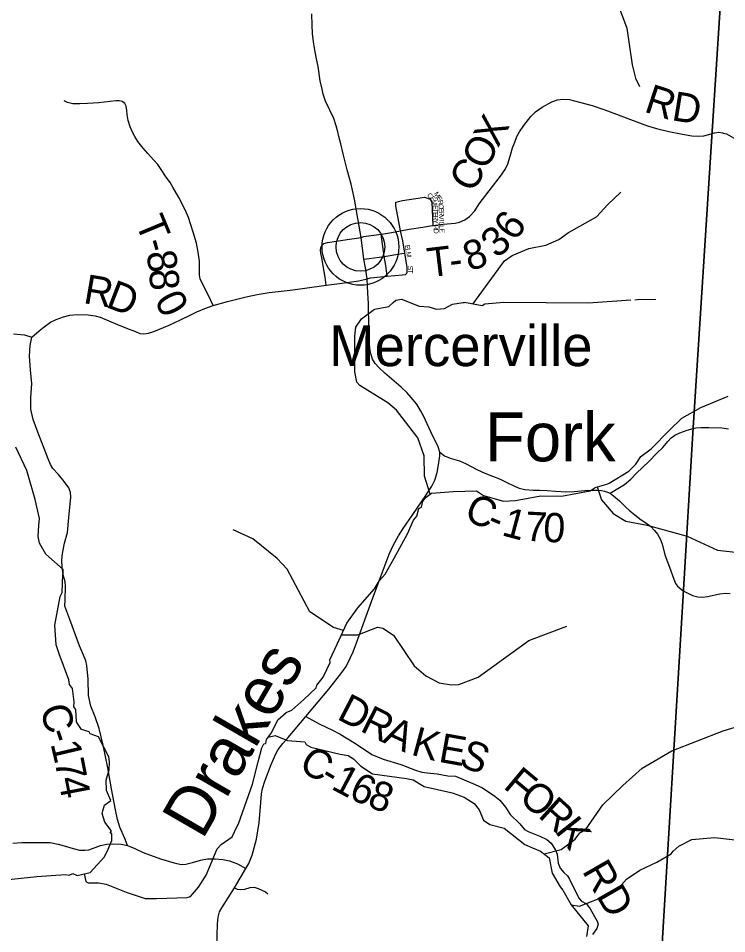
# Model space of a CAD drawing. Extents: x -1.8 to 75.7, y -2 to 25.
# Drawn here: x 46.582 to 47.955, y 16.82 to 18.595 of the extents above; entities that cross this region are included whole.
import ezdxf

# ---------------------------------------------------------------- set-up
doc = ezdxf.new("R2010")
doc.units = 0
for name, color, linetype in [('GM_X_County_Road', 7, 'Continuous'), ('GM_X_County_Road_Text', 7, 'Continuous'), ('GM_X_Minor_River', 7, 'Continuous'), ('GM_X_Minor_River_Text', 7, 'Continuous'), ('GM_X_State_Route', 7, 'Continuous'), ('GM_X_Township', 7, 'Continuous'), ('GM_X_Township_Road', 7, 'Continuous'), ('GM_X_Township_Road_Text', 7, 'Continuous'), ('GM_X_Township_Subdivision', 7, 'Continuous'), ('GM_X_Township_Subdivision_Text', 7, 'Continuous'), ('GM_X_Unincorporated', 7, 'Continuous'), ('GM_X_Unincorporated_Location', 7, 'Continuous'), ('GM_X_Unincorporated_Text', 7, 'Continuous')]:
    doc.layers.add(name, color=color, linetype=linetype)

msp = doc.modelspace()

# ---------------------------------------------------------------- linework, layer by layer
at = {"layer": 'GM_X_County_Road'}
for points in [[(46.9314, 18.0271), (46.9439, 18.032), (46.9596, 18.038), (46.9876, 18.0457), (47.0236, 18.0547), (47.0452, 18.0594), (47.0686, 18.0629), (47.1088, 18.0679), (47.1373, 18.0714), (47.1791, 18.0773), (47.2048, 18.0808), (47.2424, 18.0858), (47.2582, 18.0897)], [(46.5726, 17.9832), (46.5938, 17.9811), (46.6081, 17.9768), (46.6226, 17.9887), (46.6323, 17.9969), (46.6447, 18.0055), (46.6552, 18.0108), (46.6694, 18.016), (46.682, 18.019), (46.6968, 18.0207), (46.7173, 18.0198), (46.7308, 18.0181), (46.7409, 18.0153), (46.7576, 18.0083), (46.7743, 18.001), (46.7917, 17.9941), (46.809, 17.9877), (46.8176, 17.9834), (46.8251, 17.983), (46.8343, 17.9845), (46.8448, 17.9879), (46.8743, 18.0001), (46.8966, 18.01), (46.9167, 18.02), (46.9294, 18.0262), (46.9314, 18.0271)], [(46.7936, 16.9909), (46.7883, 17.0042), (46.7788, 17.0262), (46.7744, 17.0411), (46.7707, 17.0601), (46.7628, 17.101), (46.7557, 17.1412), (46.7469, 17.1857), (46.7388, 17.2178), (46.7311, 17.2402), (46.7229, 17.2611), (46.7179, 17.2818), (46.7177, 17.3135), (46.7152, 17.3397), (46.7133, 17.3489), (46.7084, 17.3599), (46.7007, 17.3782), (46.682, 17.4292), (46.6726, 17.4547), (46.673, 17.467), (46.6734, 17.4928), (46.6732, 17.5024), (46.6699, 17.5134), (46.6673, 17.5299), (46.6664, 17.5451), (46.6675, 17.5572), (46.6719, 17.5772), (46.6772, 17.5975), (46.68, 17.6272), (46.684, 17.6663), (46.6833, 17.6754), (46.68, 17.6844), (46.671, 17.6969), (46.6602, 17.7103), (46.6492, 17.722), (46.6448, 17.7299), (46.6402, 17.7407), (46.62, 17.7924), (46.611, 17.817), (46.6066, 17.837), (46.6066, 17.8599), (46.6081, 17.8859), (46.6059, 17.9134), (46.6039, 17.9396), (46.605, 17.9602), (46.6081, 17.9768)], [(47.399, 17.7533), (47.4085, 17.7467), (47.4191, 17.7422), (47.4374, 17.7368), (47.4491, 17.7314), (47.4707, 17.7199), (47.4866, 17.7127), (47.501, 17.7072), (47.5147, 17.7016), (47.528, 17.6957), (47.5436, 17.6876), (47.5528, 17.6838), (47.5639, 17.6811), (47.5804, 17.6801), (47.5922, 17.6801), (47.6075, 17.6793), (47.6231, 17.6779), (47.6432, 17.6767), (47.6595, 17.6772), (47.6802, 17.679), (47.6945, 17.6799), (47.7044, 17.6799), (47.7125, 17.679), (47.7186, 17.6779), (47.7241, 17.6761), (47.7291, 17.6743), (47.736, 17.6689), (47.7473, 17.6589), (47.7595, 17.6469), (47.7672, 17.6397), (47.7769, 17.6322), (47.7894, 17.6226), (47.7988, 17.6167), (47.8081, 17.6094), (47.8156, 17.6015), (47.8212, 17.5943), (47.8269, 17.5841), (47.8309, 17.5735), (47.8354, 17.5545), (47.8445, 17.5304), (47.8528, 17.5076), (47.856, 17.4992), (47.8599, 17.4935), (47.868, 17.4868), (47.8714, 17.4849), (47.8758, 17.4823)], [(47.8758, 17.4823), (47.8773, 17.4814), (47.8892, 17.4759), (47.8996, 17.473), (47.9086, 17.4726), (47.9181, 17.4739), (47.9418, 17.4789), (47.9527, 17.4804), (47.9617, 17.4796)], [(47.1395, 17.2413), (47.165, 17.227), (47.191, 17.2146), (47.206, 17.2065), (47.2324, 17.1905), (47.251, 17.178), (47.2672, 17.1674), (47.2895, 17.1584), (47.3237, 17.1482), (47.3518, 17.137), (47.3645, 17.133), (47.3744, 17.1319), (47.3941, 17.13), (47.4146, 17.126), (47.4294, 17.1252), (47.4461, 17.1184), (47.4674, 17.1093), (47.4816, 17.1026), (47.5061, 17.0863), (47.5156, 17.0789), (47.5262, 17.065), (47.5353, 17.0508), (47.5545, 17.033), (47.5635, 17.0217), (47.5703, 17.018), (47.5927, 17.0092), (47.6065, 17.0028), (47.6153, 16.9952), (47.6234, 16.9819), (47.6268, 16.9739), (47.6287, 16.9563), (47.6322, 16.9468), (47.6394, 16.9382), (47.6468, 16.9318), (47.6508, 16.9253), (47.6631, 16.9003), (47.6694, 16.8881), (47.6739, 16.8828), (47.6832, 16.8775), (47.6904, 16.8678), (47.7039, 16.8441), (47.7064, 16.8384), (47.7035, 16.83), (47.6954, 16.8181)], [(46.5718, 16.9953), (46.589, 16.9966), (46.6277, 16.9966), (46.6439, 16.9966), (46.6596, 16.9933), (46.6752, 16.9889), (46.6837, 16.9863), (46.7009, 16.9815), (46.711, 16.9815), (46.7191, 16.9826), (46.7313, 16.9872), (46.7412, 16.9907), (46.7536, 16.9935), (46.7652, 16.9942), (46.7816, 16.9933), (46.7936, 16.9909), (46.808, 16.9848), (46.824, 16.9773), (46.8579, 16.9651), (46.8839, 16.9575), (46.8981, 16.9542), (46.9066, 16.9546), (46.9195, 16.9577), (46.935, 16.9623), (46.9488, 16.9647), (46.9634, 16.9649), (46.9785, 16.9636), (46.9916, 16.9609), (47.0069, 16.955), (47.0231, 16.9461)]]:
    msp.add_lwpolyline(points, dxfattribs=at)
at = {"layer": 'GM_X_Minor_River'}
for points in [[(47.6284, 18.7505), (47.6904, 18.7156), (47.7165, 18.6675), (47.7418, 18.6293), (47.7619, 18.5758), (47.7722, 18.5049), (47.7784, 18.4791), (47.7861, 18.4628)], [(47.4633, 18.0407), (47.5246, 18.1243), (47.5393, 18.1352), (47.5715, 18.1486), (47.6046, 18.1552), (47.6298, 18.1658), (47.6484, 18.1796), (47.7026, 18.2101), (47.7249, 18.2337), (47.7498, 18.2576)], [(47.3806, 17.6723), (47.3695, 17.707), (47.3688, 17.7462), (47.3566, 17.7811), (47.3151, 17.8348), (47.2982, 17.849), (47.2544, 17.8763), (47.244, 17.8831), (47.2386, 17.8893), (47.2342, 17.9092), (47.2344, 17.9783), (47.2361, 17.9961), (47.2472, 18.0124), (47.2723, 18.031), (47.3001, 18.0358), (47.309, 18.0435), (47.3137, 18.0483), (47.3251, 18.0502), (47.3594, 18.0366), (47.3776, 18.0356), (47.3929, 18.0309), (47.4081, 18.032), (47.4238, 18.0406), (47.4443, 18.0437), (47.4473, 18.0436)], [(47.7697, 18.0481), (47.6874, 18.0428), (47.5233, 18.0435), (47.4866, 18.0408), (47.4812, 18.0376), (47.447, 18.0436)], [(47.8178, 18.0497), (47.782, 18.0489), (47.777, 18.0486)], [(46.7096, 16.9357), (46.7132, 16.9213), (46.7178, 16.9186), (46.7374, 16.9183), (46.7522, 16.916), (46.7911, 16.9002), (46.8282, 16.8881), (46.8501, 16.8881), (46.9095, 16.8898), (46.9159, 16.8921), (46.9317, 16.91), (46.9465, 16.9336), (46.9676, 16.9842), (46.9751, 16.993), (46.9967, 17.0074), (47.0065, 17.0284), (47.0091, 17.0326), (47.0359, 17.1101), (47.0472, 17.1531), (47.054, 17.1801), (47.0581, 17.1877), (47.0619, 17.1889), (47.0634, 17.1961), (47.0732, 17.2094), (47.0849, 17.2345), (47.1015, 17.249), (47.1121, 17.2532), (47.1355, 17.2738), (47.1597, 17.2963), (47.1608, 17.302), (47.1714, 17.3149), (47.1737, 17.3187), (47.1869, 17.3457), (47.1861, 17.3511), (47.2001, 17.3815), (47.2189, 17.4222), (47.2405, 17.4515), (47.2726, 17.4888), (47.282, 17.5045), (47.293, 17.517), (47.3107, 17.5482), (47.3364, 17.595), (47.348, 17.6217), (47.3545, 17.6297), (47.3586, 17.6445), (47.3635, 17.6468), (47.3665, 17.6586), (47.373, 17.6662), (47.3752, 17.6685), (47.3832, 17.6742), (47.4247, 17.6773), (47.4701, 17.6789), (47.4837, 17.6695), (47.5223, 17.6585), (47.5457, 17.6601), (47.5952, 17.669), (47.6353, 17.6683), (47.6909, 17.6787), (47.7003, 17.6852), (47.7226, 17.6913), (47.7271, 17.6932), (47.7657, 17.7165), (47.7789, 17.7302), (47.7887, 17.7451), (47.8091, 17.7603), (47.8442, 17.7961), (47.868, 17.8197), (47.9051, 17.8403), (47.958, 17.8621)], [(46.6614, 17.3624), (46.6553, 17.3802), (46.6527, 17.4179), (46.6632, 17.4738), (46.667, 17.4814), (46.6681, 17.5171), (46.6692, 17.5194), (46.6688, 17.5258), (46.6352, 17.5558), (46.623, 17.577), (46.6204, 17.59), (46.6222, 17.6112), (46.623, 17.6249), (46.615, 17.6621), (46.5987, 17.718), (46.5775, 17.7635)], [(47.704, 17.6862), (47.7124, 17.6613), (47.7354, 17.6348), (47.7598, 17.6197), (47.8008, 17.612), (47.8787, 17.5904), (47.9373, 17.5637), (48.008, 17.5557), (48.0418, 17.5475), (48.0547, 17.5407), (48.0677, 17.5252), (48.0895, 17.498), (48.1198, 17.4481), (48.1434, 17.4315), (48.1571, 17.4262), (48.2033, 17.3938), (48.2139, 17.3885), (48.2371, 17.3841), (48.2523, 17.3827), (48.3137, 17.3974)], [(47.2123, 17.4078), (47.1929, 17.4133), (47.1472, 17.4439), (47.103, 17.5264), (47.0839, 17.5476), (47.0366, 17.5853), (46.9986, 17.603)], [(47.2083, 17.3993), (47.24, 17.3992), (47.2786, 17.4145), (47.2885, 17.4123), (47.3095, 17.3987), (47.3497, 17.3393), (47.3722, 17.3201), (47.3981, 17.3066), (47.422, 17.3021), (47.4357, 17.303), (47.4732, 17.3176), (47.5718, 17.3887), (47.6452, 17.4164)], [(46.5575, 16.9243), (46.618, 16.9306), (46.6735, 16.9349), (46.6807, 16.9334), (46.6879, 16.9364), (46.6962, 16.9326), (46.7212, 16.9384), (46.7491, 16.9692), (46.7563, 16.9837), (46.7631, 17.0004), (46.7634, 17.0141), (46.7604, 17.0149), (46.7623, 17.0183), (46.7619, 17.0202), (46.7498, 17.0361), (46.7449, 17.0532), (46.746, 17.0578), (46.7494, 17.0692), (46.7615, 17.078), (46.7528, 17.0973), (46.7524, 17.1175), (46.7584, 17.1376), (46.7591, 17.1528), (46.7576, 17.1627), (46.7375, 17.2018), (46.7213, 17.2075), (46.7194, 17.2116), (46.7046, 17.2158), (46.6967, 17.2276), (46.6948, 17.2306), (46.6936, 17.2545), (46.6895, 17.2595), (46.6902, 17.2697), (46.6872, 17.2952), (46.6811, 17.3032), (46.68, 17.3123), (46.6614, 17.3624)], [(47.6013, 16.9744), (47.6346, 16.9831), (47.6614, 17.0034), (47.6705, 17.0152), (47.6814, 17.0213), (47.7149, 17.0697), (47.7542, 17.1075), (47.7915, 17.1411), (47.849, 17.1744), (47.9482, 17.2129), (47.9865, 17.2249), (48.0221, 17.2304)], [(47.0667, 17.2012), (47.0798, 17.2041), (47.1041, 17.1942), (47.1373, 17.1916), (47.1398, 17.187), (47.1494, 17.1814), (47.2063, 17.1678)], [(47.2063, 17.1678), (47.2215, 17.1654), (47.2319, 17.159), (47.2458, 17.1445), (47.2688, 17.1297), (47.3343, 17.1208), (47.3475, 17.1181), (47.369, 17.1052), (47.4204, 17.0937), (47.4249, 17.0924), (47.4466, 17.0845), (47.4655, 17.0722), (47.4757, 17.0601), (47.4838, 17.0397), (47.496, 17.0313), (47.5238, 17.0243), (47.564, 16.9927), (47.5786, 16.9861), (47.5943, 16.98), (47.6109, 16.9669), (47.6171, 16.9371), (47.6326, 16.9104), (47.6377, 16.9045), (47.6535, 16.8759), (47.687, 16.835), (47.6834, 16.8146)], [(47.6537, 16.8756), (47.67, 16.8731), (47.7259, 16.8949), (47.7514, 16.9149), (47.7612, 16.9253), (47.787, 16.943), (47.8196, 16.9583), (47.8474, 16.9749), (47.8513, 16.9801), (47.8625, 16.9896), (47.8875, 17.0025), (47.9318, 17.0064), (47.9718, 17.0017)]]:
    msp.add_lwpolyline(points, dxfattribs=at)
at = {"layer": 'GM_X_State_Route'}
for points in [[(47.3918, 17.7721), (47.3849, 17.7862), (47.3679, 17.8226), (47.3619, 17.8344), (47.3543, 17.8464), (47.3437, 17.8598), (47.3353, 17.869), (47.3244, 17.8794), (47.2924, 17.9067), (47.2813, 17.9174), (47.2741, 17.9255), (47.2689, 17.9338), (47.2666, 17.9404), (47.2646, 17.9467), (47.2635, 17.9555), (47.2623, 17.97), (47.2614, 17.996), (47.2606, 18.0415), (47.2598, 18.0626), (47.2591, 18.0758), (47.2582, 18.0897), (47.255, 18.1113), (47.2518, 18.1278), (47.2465, 18.1698), (47.2356, 18.2326), (47.2341, 18.2411), (47.2312, 18.2557), (47.2273, 18.2732), (47.2198, 18.3014), (47.2119, 18.3321), (47.2072, 18.3517), (47.2034, 18.366), (47.2015, 18.3748), (47.198, 18.3863), (47.1934, 18.4005), (47.186, 18.4171), (47.1778, 18.4344), (47.1729, 18.4478), (47.1708, 18.4575), (47.1675, 18.4735), (47.1631, 18.5013), (47.1602, 18.5162), (47.1577, 18.5296), (47.1544, 18.5496), (47.1526, 18.5652), (47.1517, 18.5815), (47.151, 18.6034)], [(47.3825, 17.6859), (47.3837, 17.6876), (47.3892, 17.699), (47.3939, 17.7142), (47.3968, 17.7289), (47.399, 17.7463), (47.399, 17.7533), (47.3958, 17.7639), (47.3918, 17.7721)], [(46.9667, 16.7953), (46.968, 16.839), (46.9693, 16.8519), (46.9722, 16.8624), (46.9766, 16.8702), (47.001, 16.9089), (47.0231, 16.9461), (47.0287, 16.9559), (47.0357, 16.972), (47.0439, 17.003), (47.0492, 17.0356), (47.0518, 17.066), (47.0537, 17.0909), (47.0556, 17.1017), (47.0597, 17.1154), (47.0722, 17.148), (47.0811, 17.1687), (47.086, 17.1769), (47.0949, 17.1884), (47.1049, 17.2002), (47.1395, 17.2413), (47.1633, 17.2694), (47.1839, 17.2942), (47.2095, 17.3261), (47.2175, 17.3382), (47.2263, 17.3554), (47.231, 17.3664), (47.2375, 17.3838), (47.2668, 17.4643), (47.2875, 17.5195), (47.301, 17.556), (47.3088, 17.5729), (47.319, 17.5912), (47.3284, 17.6057), (47.3468, 17.6325), (47.3718, 17.6695), (47.3825, 17.6859)]]:
    msp.add_lwpolyline(points, dxfattribs=at)
at = {"layer": 'GM_X_Township'}
for points in [[(47.7632, 15.7121), (47.7893, 16.1371), (47.8138, 16.5363), (47.826, 16.7363), (47.8708, 17.4759), (47.8899, 17.791), (47.9266, 18.366), (47.9522, 18.7663), (47.1815, 18.806), (46.9192, 18.8195), (46.3714, 18.8466), (46.1197, 18.859), (45.3865, 18.8952), (44.8356, 18.9224), (43.8002, 18.978)], [(50.6002, 18.6397), (50.591, 18.6401), (50.1896, 18.6602), (49.0051, 18.7193), (48.8964, 18.7242), (47.9522, 18.7663), (47.9266, 18.366), (47.8899, 17.791), (47.8708, 17.4759), (47.826, 16.7363), (47.8138, 16.5363), (47.7893, 16.1371), (47.7632, 15.7121)]]:
    msp.add_lwpolyline(points, dxfattribs=at)
at = {"layer": 'GM_X_Township_Road'}
for points in [[(46.9335, 18.1048), (46.9334, 18.1091), (46.9334, 18.1241), (46.9309, 18.1413), (46.9274, 18.159), (46.9212, 18.1804), (46.9122, 18.2085), (46.9056, 18.2233), (46.893, 18.2475), (46.8818, 18.2676), (46.8762, 18.2766), (46.8675, 18.289), (46.8591, 18.3017), (46.8527, 18.3111), (46.8443, 18.3207), (46.833, 18.3329), (46.824, 18.3434), (46.8141, 18.3563), (46.8079, 18.3655), (46.8032, 18.3743), (46.7989, 18.3845), (46.7951, 18.3965), (46.7929, 18.4085), (46.7923, 18.4164), (46.7912, 18.4248), (46.7884, 18.4297), (46.7837, 18.4336), (46.7777, 18.4351), (46.7709, 18.4346), (46.7385, 18.4312), (46.7161, 18.4297), (46.7011, 18.4291), (46.6878, 18.4293), (46.6775, 18.4314), (46.6713, 18.4346)], [(47.2853, 18.1763), (47.2987, 18.1781), (47.323, 18.1827), (47.34, 18.1857), (47.3661, 18.1901), (47.3765, 18.1919), (47.3856, 18.1933), (47.4055, 18.1954), (47.4286, 18.1977), (47.4371, 18.1997), (47.4476, 18.2044), (47.4568, 18.2106), (47.4667, 18.2215), (47.4755, 18.2352), (47.4949, 18.2606), (47.5187, 18.2915), (47.5264, 18.3032), (47.5309, 18.3124), (47.5358, 18.3274), (47.5403, 18.3437), (47.5446, 18.355), (47.5486, 18.3655), (47.5537, 18.3745), (47.5619, 18.3871), (47.5754, 18.4047), (47.5846, 18.4134), (47.5974, 18.4224), (47.6165, 18.4329), (47.627, 18.4368), (47.6379, 18.4378), (47.6507, 18.4372), (47.6702, 18.4325), (47.6944, 18.4256), (47.717, 18.4181), (47.7416, 18.4092), (47.7639, 18.4006), (47.7859, 18.3922), (47.802, 18.3867), (47.8193, 18.3813), (47.8431, 18.3751), (47.8696, 18.3704), (47.8876, 18.3672), (47.9013, 18.3664), (47.9107, 18.3672), (47.9208, 18.3698), (47.927, 18.3715), (47.9317, 18.3728), (47.9402, 18.3738), (47.9471, 18.373), (47.9487, 18.3725)], [(47.9487, 18.3725), (47.9546, 18.3708), (47.9732, 18.3604), (47.989, 18.3509), (48.007, 18.3402), (48.0166, 18.3334), (48.0262, 18.3244), (48.0352, 18.3137), (48.0446, 18.3007), (48.059, 18.2761), (48.0654, 18.266), (48.0733, 18.2585), (48.0815, 18.2544), (48.0877, 18.2517), (48.0883, 18.2516)], [(47.2465, 18.1698), (47.2516, 18.1715), (47.2853, 18.1763)], [(46.9596, 18.038), (46.9506, 18.0575), (46.9386, 18.0811), (46.9347, 18.0896), (46.9336, 18.0976), (46.9335, 18.1048)], [(47.7291, 17.6743), (47.7442, 17.6833), (47.7573, 17.6912), (47.7695, 17.7014), (47.7806, 17.7131), (47.8041, 17.7357), (47.8201, 17.7517), (47.8314, 17.7626), (47.8411, 17.7744), (47.8477, 17.7816), (47.8549, 17.7865), (47.8641, 17.7911), (47.8786, 17.7962), (47.8904, 17.7992), (47.8953, 17.8005), (47.9052, 17.8017), (47.9127, 17.8015)], [(47.9127, 17.8015), (47.9204, 17.8014), (47.9455, 17.8006), (47.959, 17.7987)], [(47.001, 16.9089), (47.0065, 16.9061), (47.0122, 16.9057), (47.0213, 16.9063), (47.0318, 16.9094), (47.0393, 16.91), (47.0471, 16.9078), (47.0615, 16.9011), (47.0655, 16.8971)]]:
    msp.add_lwpolyline(points, dxfattribs=at)
at = {"layer": 'GM_X_Township_Subdivision'}
for points in [[(47.3529, 18.2454), (47.3693, 18.2479), (47.3806, 18.244), (47.3838, 18.2385), (47.3856, 18.1933)], [(47.323, 18.1827), (47.3138, 18.2311), (47.314, 18.2385), (47.3269, 18.2414), (47.3529, 18.2454)], [(47.3342, 18.0991), (47.3353, 18.1007), (47.3361, 18.1026), (47.3358, 18.1115), (47.3317, 18.1364), (47.3312, 18.1398), (47.3275, 18.1634), (47.323, 18.1827)], [(47.1741, 18.1582), (47.1742, 18.1582), (47.1813, 18.1602), (47.1988, 18.1629), (47.2197, 18.1659), (47.2465, 18.1698)], [(47.2968, 18.095), (47.2945, 18.1157), (47.2913, 18.1329), (47.2853, 18.1763)], [(47.1791, 18.0773), (47.1768, 18.0929), (47.1729, 18.115), (47.1708, 18.1274), (47.1687, 18.1396), (47.1678, 18.1453), (47.1685, 18.1501), (47.1704, 18.1545), (47.1741, 18.1582)], [(47.2518, 18.1278), (47.2624, 18.1292), (47.2913, 18.1329), (47.3257, 18.1387), (47.3312, 18.1398)], [(47.2582, 18.0897), (47.2649, 18.0916), (47.2968, 18.095), (47.3269, 18.0976), (47.3324, 18.098), (47.3342, 18.0991)]]:
    msp.add_lwpolyline(points, dxfattribs=at)
at = {"layer": 'GM_X_Unincorporated'}
for radius in [0.0744, 0.0472]:
    msp.add_circle((47.2453, 18.1517), radius, dxfattribs=at)
at = {"layer": 'GM_X_Unincorporated_Location'}
msp.add_line((47.2453, 18.1517), (47.2453, 18.1517), dxfattribs=at)

# ---------------------------------------------------------------- texts
at = {"layer": 'GM_X_County_Road_Text'}
for s, height, rotation, p in [('R', 0.0568, 350.3214, (46.7066, 18.0429)), ('D', 0.0568, 338.9366, (46.7497, 18.0358)), ('C', 0.0568, 336.0016, (47.4436, 17.6244)), ('-', 0.0568, 336.7539, (47.487, 17.6051)), ('1', 0.0568, 345.0845, (47.517, 17.5929)), ('7', 0.0568, 357.1207, (47.5636, 17.5819)), ('0', 0.0568, 356.7979, (47.5985, 17.5801)), ('D', 0.0568, 332.6448, (47.1975, 17.2371)), ('C', 0.0568, 285.9744, (46.6235, 17.2567)), ('R', 0.0568, 333.3021, (47.2425, 17.2138)), ('A', 0.0568, 335.2103, (47.2861, 17.1919)), ('K', 0.0568, 345.0795, (47.3415, 17.1673)), ('-', 0.0568, 288.6765, (46.6372, 17.2091)), ('E', 0.0568, 349.8639, (47.3949, 17.1534)), ('1', 0.0568, 283.2417, (46.6443, 17.1884)), ('S', 0.0568, 337.7336, (47.4337, 17.1468)), ('C', 0.0568, 328.6259, (47.123, 17.1396)), ('7', 0.0568, 281.139, (46.6522, 17.1548)), ('-', 0.0568, 329.6337, (47.1638, 17.1147)), ('1', 0.0568, 332.1583, (47.1863, 17.1016)), ('6', 0.0568, 335.1745, (47.2202, 17.0838)), ('F', 0.0568, 320.2334, (47.5203, 17.1036)), ('4', 0.0568, 280.916, (46.659, 17.1205)), ('8', 0.0568, 339.4981, (47.2563, 17.0673)), ('O', 0.0568, 320.2299, (47.5498, 17.0791)), ('R', 0.0568, 318.0746, (47.5878, 17.0475)), ('K', 0.0568, 308.2394, (47.6207, 17.0182)), ('RD', 0.05682, 299.8686, (47.674, 16.9415))]:
    msp.add_text(s, height=height, rotation=rotation, dxfattribs=at).set_placement(p)
at = {"layer": 'GM_X_Minor_River_Text'}
for s, height, rotation, p in [('Fork', 0.0947, 359.9962, (47.4866, 17.7359)), ('Drakes', 0.09469, 59.9948, (46.9387, 17.0001))]:
    msp.add_text(s, height=height, rotation=rotation, dxfattribs=at).set_placement(p)
at = {"layer": 'GM_X_Township_Road_Text'}
for s, rotation, p in [('R', 341.8292, (47.7932, 18.4144)), ('D', 350.8483, (47.8469, 18.3976)), ('X', 62.0664, (47.5119, 18.3425)), ('O', 62.6275, (47.489, 18.2982)), ('C', 57.9501, (47.4617, 18.2542)), ('T', 292.5216, (46.8081, 18.1989)), ('6', 53.6809, (47.5448, 18.1605)), ('3', 41.9178, (47.5103, 18.1277)), ('-', 285.7953, (46.8238, 18.1613)), ('8', 19.4828, (47.4566, 18.1037)), ('8', 279.6839, (46.8298, 18.1404)), ('T', 6.8885, (47.378, 18.0925)), ('-', 7.4441, (47.4208, 18.0977)), ('8', 274.0676, (46.8355, 18.1074)), ('0', 297.5303, (46.8448, 18.0482))]:
    msp.add_text(s, height=0.0568, rotation=rotation, dxfattribs=at).set_placement(p)
at = {"layer": 'GM_X_Township_Subdivision_Text'}
for s, rotation, p in [('C', 328.8363, (47.3737, 18.2491)), ('E', 307.6402, (47.3795, 18.2458)), ('M', 300.2532, (47.3872, 18.2552)), ('E', 300.2397, (47.3922, 18.2466)), ('M', 283.6055, (47.3831, 18.2415)), ('E', 273.007, (47.3854, 18.2322)), ('R', 281.0194, (47.3953, 18.2416)), ('C', 272.1863, (47.3967, 18.2346)), ('T', 272.2682, (47.3857, 18.2256)), ('E', 272.2136, (47.386, 18.2189)), ('E', 272.2088, (47.397, 18.2271)), ('R', 272.2105, (47.3972, 18.2205)), ('V', 272.1862, (47.3975, 18.213)), ('R', 272.1863, (47.3862, 18.2123)), ('Y', 272.2077, (47.3865, 18.2048)), ('I', 272.2173, (47.3978, 18.2046)), ('L', 272.1863, (47.398, 18.2005)), ('R', 272.2105, (47.3869, 18.194)), ('D', 272.2081, (47.3872, 18.1865)), ('L', 272.2153, (47.3982, 18.1938)), ('E', 272.2136, (47.3985, 18.1871)), ('E', 278.2248, (47.3313, 18.1548)), ('L', 278.1977, (47.3323, 18.1482)), ('M', 281.6945, (47.3333, 18.141)), ('S', 272.9791, (47.3372, 18.1148)), ('T', 269.4262, (47.3375, 18.1083))]:
    msp.add_text(s, height=0.00947, rotation=rotation, dxfattribs=at).set_placement(p)
at = {"layer": 'GM_X_Unincorporated_Text'}
msp.add_text('Mercerville', height=0.078977, rotation=0, dxfattribs=at).set_placement((47.1846, 17.9204))

doc.saveas('drawing.dxf')
